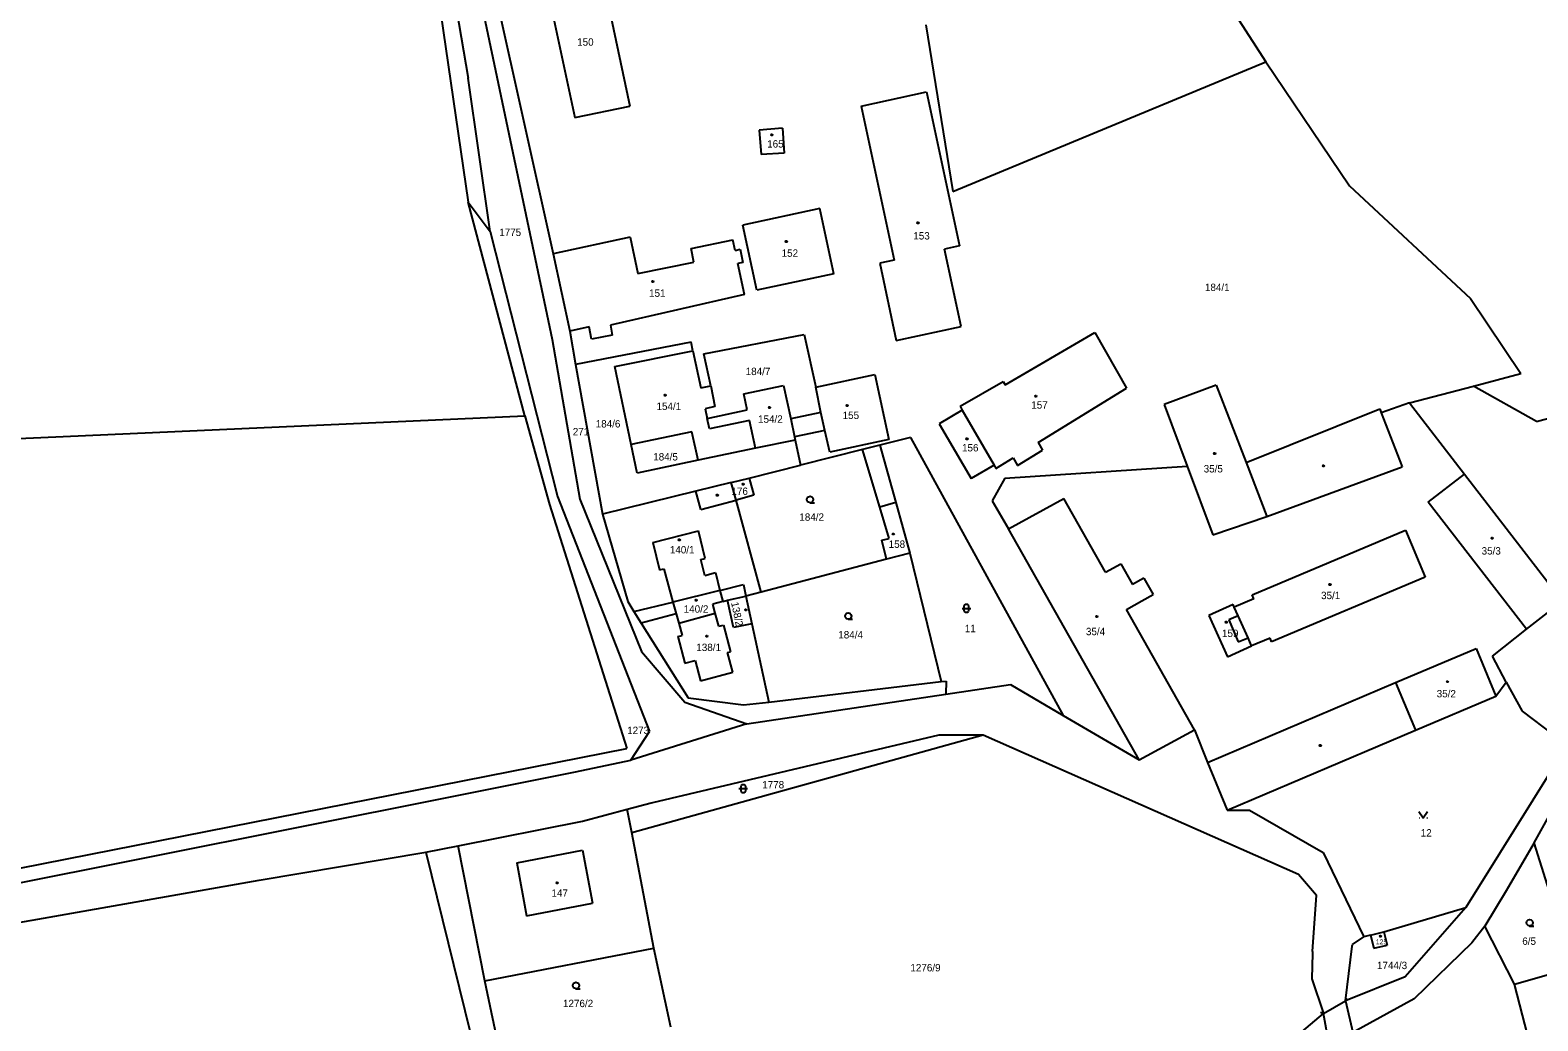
# Model space of a CAD drawing. Extents: x -799786 to -795190, y -1021716 to -1017834.
# Drawn here: x -798278.5 to -797930.9, y -1018937.1 to -1018708.6 of the extents above; entities that cross this region are included whole.
import ezdxf

# ---------------------------------------------------------------- set-up
doc = ezdxf.new("R2010")
doc.units = 0
for name, color, linetype in [('Default', 7, 'Continuous'), ('KN_HRANICE', 7, 'Continuous'), ('KN_KULTURY', 7, 'Continuous'), ('KN_PARCELY', 7, 'Continuous'), ('KN_SLUCKY', 7, 'Continuous')]:
    doc.layers.add(name, color=color, linetype=linetype)

# ---------------------------------------------------------------- blocks, each defined once
blk = doc.blocks.new('304')
at = {"layer": 'Default'}
blk.add_lwpolyline([(0, 0), (-0.38, 0.1), (-0.65, 0.37), (-0.75, 0.74), (-0.65, 1.11), (-0.38, 1.38), (-0.01, 1.48), (0.36, 1.38), (0.63, 1.11), (0.73, 0.73), (0.63, 0.35), (0.36, 0.08), (-0.02, -0.02), (0.98, -0.02)], dxfattribs=at)
blk = doc.blocks.new('314')
at = {"layer": 'Default'}
for p, q in [((-0.95, 0), (-0.85, 0)), ((0.85, 0), (0.95, 0))]:
    blk.add_line(p, q, dxfattribs=at)
blk.add_lwpolyline([(-1, 1.5), (0, 0), (1, 1.5)], dxfattribs=at)
blk = doc.blocks.new('316')
at = {"layer": 'Default'}
for points in [[(-1, 1), (0.27, 1), (1, 1)], [(-0.5, 1.5), (-0.4, 1.79), (-0.15, 1.97), (0.16, 1.97), (0.41, 1.79), (0.51, 1.5), (0.51, 0.5), (0.41, 0.21), (0.16, 0.03), (-0.15, 0.03), (-0.4, 0.21), (-0.5, 0.5), (-0.5, 1.5)]]:
    blk.add_lwpolyline(points, dxfattribs=at)
blk = doc.blocks.new('402')
at = {"layer": 'Default'}
blk.add_lwpolyline([(0.09, 0.15), (0.18, 0), (0.09, -0.15), (-0.09, -0.15), (-0.18, 0), (-0.09, 0.15), (0.09, 0.15)], dxfattribs=at)
blk = doc.blocks.new('4201')
at = {"layer": 'Default'}
blk.add_line((0, 0), (-0.5, -0.5), dxfattribs=at)

msp = doc.modelspace()

# ---------------------------------------------------------------- linework, layer by layer
at = {"layer": 'KN_HRANICE'}
for p, q in [((-798190.23, -1018645.2), (-798177.54, -1018719.73)), ((-798186.58, -1018644.89), (-798158.12, -1018780)), ((-798183.62, -1018644.7), (-798157.9, -1018760.22)), ((-798185.82, -1018691.03), (-798177.54, -1018748.29)), ((-798147.83, -1018690.52), (-798140.24, -1018726.2)), ((-798160.55, -1018693.06), (-798152.95, -1018728.8)), ((-798000.59, -1018705.06), (-797993.6, -1018715.91)), ((-798072.03, -1018707.41), (-798065.78, -1018745.87)), ((-798065.78, -1018745.87), (-797993.6, -1018715.91)), ((-797993.6, -1018715.91), (-797974.27, -1018744.5)), ((-798172.45, -1018755.08), (-798177.54, -1018719.73)), ((-798086.88, -1018726.19), (-798071.86, -1018722.86)), ((-798071.86, -1018722.86), (-798064.24, -1018758.37)), ((-798152.95, -1018728.8), (-798140.24, -1018726.2)), ((-798086.88, -1018726.19), (-798079.27, -1018761.66)), ((-798105.03, -1018731.26), (-798110.4, -1018731.68)), ((-798110.4, -1018731.68), (-798109.96, -1018737.34)), ((-798105.03, -1018731.26), (-798104.63, -1018736.97)), ((-798104.63, -1018736.97), (-798109.96, -1018737.34)), ((-797974.27, -1018744.5), (-797946.38, -1018770.53)), ((-798177.54, -1018748.29), (-798172.45, -1018755.08)), ((-798164.43, -1018797.57), (-798177.54, -1018748.29)), ((-798096.4, -1018749.79), (-798114.16, -1018753.61)), ((-798093.17, -1018764.82), (-798096.4, -1018749.79)), ((-798110.94, -1018768.57), (-798114.16, -1018753.61)), ((-798172.45, -1018755.08), (-798156.9, -1018816.15)), ((-798140.13, -1018756.39), (-798157.9, -1018760.22)), ((-798140.13, -1018756.39), (-798138.4, -1018764.79)), ((-798126.14, -1018758.95), (-798116.52, -1018756.97)), ((-798115.99, -1018759.43), (-798116.52, -1018756.97)), ((-798157.9, -1018760.22), (-798154.1, -1018778.04)), ((-798125.49, -1018762.13), (-798126.14, -1018758.95)), ((-798115.99, -1018759.43), (-798114.78, -1018759.18)), ((-798114.78, -1018759.18), (-798114.16, -1018762.18)), ((-798079.27, -1018761.66), (-798082.63, -1018762.4)), ((-798064.24, -1018758.37), (-798067.67, -1018759.12)), ((-798063.84, -1018777), (-798067.67, -1018759.12)), ((-798138.4, -1018764.79), (-798125.49, -1018762.13)), ((-798114.16, -1018762.18), (-798115.35, -1018762.42)), ((-798113.8, -1018769.59), (-798115.35, -1018762.42)), ((-798093.17, -1018764.82), (-798110.94, -1018768.57)), ((-798082.63, -1018762.4), (-798078.87, -1018780.22)), ((-798113.8, -1018769.59), (-798144.73, -1018776.67)), ((-797946.38, -1018770.53), (-797934.78, -1018787.83)), ((-798149.62, -1018777.07), (-798154.1, -1018778.04)), ((-798154.1, -1018778.04), (-798152.76, -1018785.75)), ((-798149.06, -1018779.92), (-798149.62, -1018777.07)), ((-798144.28, -1018778.95), (-798149.06, -1018779.92)), ((-798144.73, -1018776.67), (-798144.28, -1018778.95)), ((-798123.16, -1018783.29), (-798100.01, -1018778.8)), ((-798100.01, -1018778.8), (-798097.32, -1018790.95)), ((-798078.87, -1018780.22), (-798063.84, -1018777)), ((-798053.72, -1018790.43), (-798033.01, -1018778.36)), ((-798033.01, -1018778.36), (-798025.69, -1018791.2)), ((-798158.12, -1018780), (-798151.74, -1018816.81)), ((-798126.08, -1018780.59), (-798152.76, -1018785.75)), ((-798143.73, -1018786.2), (-798125.71, -1018782.56)), ((-798125.71, -1018782.56), (-798126.08, -1018780.59)), ((-798125.71, -1018782.56), (-798123.85, -1018791.14)), ((-798152.76, -1018785.75), (-798146.54, -1018820.24)), ((-798121.59, -1018790.63), (-798123.16, -1018783.29)), ((-798139.94, -1018804.21), (-798143.73, -1018786.2)), ((-798097.32, -1018790.95), (-798083.73, -1018788.02)), ((-798083.73, -1018788.02), (-798080.55, -1018803.03)), ((-797945.75, -1018790.73), (-797934.78, -1018787.83)), ((-798123.85, -1018791.14), (-798121.59, -1018790.63)), ((-798121.59, -1018790.63), (-798120.63, -1018795.46)), ((-798113.96, -1018792.51), (-798104.82, -1018790.56)), ((-798113.17, -1018796.22), (-798113.96, -1018792.51)), ((-798104.82, -1018790.56), (-798103.16, -1018798.25)), ((-798096.18, -1018796.81), (-798097.32, -1018790.95)), ((-798064.09, -1018795.36), (-798054.18, -1018789.63)), ((-798054.18, -1018789.63), (-798053.72, -1018790.43)), ((-798046.07, -1018803.73), (-798025.69, -1018791.2)), ((-798005.03, -1018790.47), (-798017.07, -1018794.94)), ((-798005.03, -1018790.47), (-797998.15, -1018808.32)), ((-797960.46, -1018794.61), (-797945.75, -1018790.73)), ((-797931.22, -1018798.88), (-797945.75, -1018790.73)), ((-797931.22, -1018798.88), (-797908.42, -1018792.81)), ((-798120.63, -1018795.46), (-798122.88, -1018795.94)), ((-798122.88, -1018795.94), (-798122.4, -1018798.19)), ((-798122.4, -1018798.19), (-798113.17, -1018796.22)), ((-798063.58, -1018796.25), (-798068.95, -1018799.39)), ((-798064.09, -1018795.36), (-798063.58, -1018796.25)), ((-798063.58, -1018796.25), (-798056.26, -1018808.98)), ((-798017.07, -1018794.94), (-798011.74, -1018809.21)), ((-797998.15, -1018808.32), (-797967.29, -1018795.96)), ((-797967.29, -1018795.96), (-797966.98, -1018796.9)), ((-797960.46, -1018794.61), (-797966.98, -1018796.9)), ((-797960.46, -1018794.61), (-797947.79, -1018811.02)), ((-798648.58, -1018819.28), (-798164.43, -1018797.57)), ((-798164.43, -1018797.57), (-798158.8, -1018818.01)), ((-798121.89, -1018800.59), (-798122.4, -1018798.19)), ((-798112.65, -1018798.62), (-798121.89, -1018800.59)), ((-798111.25, -1018805.07), (-798112.65, -1018798.62)), ((-798096.18, -1018796.81), (-798103.16, -1018798.25)), ((-798103.16, -1018798.25), (-798102.26, -1018802.39)), ((-798068.95, -1018799.39), (-798061.53, -1018812.06)), ((-798125.93, -1018801.3), (-798139.94, -1018804.21)), ((-798124.51, -1018807.83), (-798125.93, -1018801.3)), ((-798102.09, -1018803.18), (-798111.25, -1018805.07)), ((-798095.26, -1018800.95), (-798102.26, -1018802.39)), ((-798102.26, -1018802.39), (-798102.09, -1018803.18)), ((-798102.09, -1018803.18), (-798100.92, -1018808.97)), ((-798094.16, -1018805.93), (-798095.26, -1018800.95)), ((-798080.55, -1018803.03), (-798094.16, -1018805.93)), ((-798075.54, -1018802.58), (-798082.57, -1018804.35)), ((-798075.54, -1018802.58), (-798040.31, -1018866.67)), ((-798138.54, -1018810.77), (-798139.94, -1018804.21)), ((-798111.25, -1018805.07), (-798124.51, -1018807.83)), ((-798086.58, -1018805.36), (-798100.92, -1018808.97)), ((-798082.57, -1018804.35), (-798086.58, -1018805.36)), ((-798082.59, -1018818.64), (-798086.58, -1018805.36)), ((-798082.57, -1018804.35), (-798078.92, -1018817.58)), ((-798050.84, -1018809), (-798045.08, -1018805.46)), ((-798046.07, -1018803.73), (-798045.08, -1018805.46)), ((-798124.51, -1018807.83), (-798138.54, -1018810.77)), ((-798112.7, -1018811.93), (-798100.92, -1018808.97)), ((-798056.26, -1018808.98), (-798061.53, -1018812.06)), ((-798056.26, -1018808.98), (-798055.83, -1018809.73)), ((-798055.83, -1018809.73), (-798051.83, -1018807.27)), ((-798053.76, -1018811.93), (-798011.74, -1018809.21)), ((-798051.83, -1018807.27), (-798050.84, -1018809)), ((-798011.74, -1018809.21), (-798005.83, -1018825.03)), ((-797998.15, -1018808.32), (-797993.34, -1018820.8)), ((-798116.86, -1018812.97), (-798125, -1018814.96)), ((-798116.86, -1018812.97), (-798112.7, -1018811.93)), ((-798115.74, -1018817.06), (-798116.86, -1018812.97)), ((-798112.7, -1018811.93), (-798111.67, -1018815.91)), ((-798053.76, -1018811.93), (-798056.73, -1018817.15)), ((-797956.14, -1018817.47), (-797947.79, -1018811.02)), ((-797947.79, -1018811.02), (-797925.16, -1018840.33)), ((-798156.9, -1018816.15), (-798135.7, -1018870.38)), ((-798151.74, -1018816.81), (-798137.57, -1018851.92)), ((-798125, -1018814.96), (-798146.54, -1018820.24)), ((-798111.67, -1018815.91), (-798115.74, -1018817.06)), ((-798109.95, -1018838.23), (-798115.74, -1018817.06)), ((-798056.73, -1018817.15), (-798052.91, -1018823.63)), ((-798052.91, -1018823.63), (-798040.17, -1018816.67)), ((-798030.58, -1018833.65), (-798040.17, -1018816.67)), ((-798158.8, -1018818.01), (-798140.92, -1018874.27)), ((-798146.54, -1018820.24), (-798140.72, -1018840.37)), ((-798080.43, -1018825.84), (-798082.59, -1018818.64)), ((-798078.92, -1018817.58), (-798075.71, -1018829.25)), ((-798005.83, -1018825.03), (-797993.34, -1018820.8)), ((-797933.51, -1018846.78), (-797956.14, -1018817.47)), ((-798022.79, -1018876.94), (-798052.91, -1018823.63)), ((-798082.17, -1018826.29), (-798080.43, -1018825.84)), ((-798081.03, -1018830.65), (-798082.17, -1018826.29)), ((-798081.03, -1018830.65), (-798109.95, -1018838.23)), ((-798075.71, -1018829.25), (-798081.03, -1018830.65)), ((-798075.71, -1018829.25), (-798068.46, -1018858.88)), ((-798030.58, -1018833.65), (-798027.06, -1018831.73)), ((-798027.06, -1018831.73), (-798024.37, -1018836.48)), ((-798119.46, -1018837.83), (-798130.3, -1018840.54)), ((-798119.46, -1018837.83), (-798114.06, -1018836.48)), ((-798114.06, -1018836.48), (-798113.49, -1018839.16)), ((-798021.71, -1018834.99), (-798024.37, -1018836.48)), ((-798021.71, -1018834.99), (-798019.54, -1018838.82)), ((-798140.72, -1018840.37), (-798139.33, -1018842.72)), ((-798139.33, -1018842.72), (-798130.3, -1018840.54)), ((-798118.78, -1018840.42), (-798121.1, -1018841.03)), ((-798120.54, -1018843.08), (-798121.1, -1018841.03)), ((-798118.78, -1018840.42), (-798117.69, -1018840.06)), ((-798117.69, -1018840.06), (-798113.49, -1018839.16)), ((-798116.34, -1018846.42), (-798117.69, -1018840.06)), ((-798109.95, -1018838.23), (-798113.49, -1018839.16)), ((-798113.49, -1018839.16), (-798112.13, -1018845.52)), ((-798025.74, -1018842.21), (-798022.21, -1018840.28)), ((-798022.21, -1018840.28), (-798019.54, -1018838.82)), ((-798001.16, -1018841.09), (-798006.75, -1018843.6)), ((-798000.89, -1018841.68), (-798001.16, -1018841.09)), ((-797999.99, -1018843.7), (-798000.89, -1018841.68)), ((-797933.51, -1018846.78), (-797925.16, -1018840.33)), ((-798139.33, -1018842.72), (-798137.64, -1018845.36)), ((-798129.56, -1018843.25), (-798137.64, -1018845.36)), ((-798129.56, -1018843.25), (-798128.98, -1018845.39)), ((-798128.98, -1018845.39), (-798120.54, -1018843.08)), ((-798010.05, -1018869.98), (-798025.74, -1018842.21)), ((-798006.75, -1018843.6), (-798002.47, -1018853.14)), ((-797997.69, -1018848.81), (-797999.99, -1018843.7)), ((-798137.64, -1018845.36), (-798126.82, -1018862.65)), ((-798112.13, -1018845.52), (-798116.34, -1018846.42)), ((-798112.13, -1018845.52), (-798108.16, -1018863.64)), ((-797941.35, -1018853.03), (-797933.51, -1018846.78)), ((-798137.57, -1018851.92), (-798127.54, -1018863.64)), ((-798002.47, -1018853.14), (-797996.88, -1018850.63)), ((-797996.88, -1018850.63), (-797997.69, -1018848.81)), ((-797963.72, -1018859.11), (-797945.11, -1018851.21)), ((-797945.11, -1018851.21), (-797940.56, -1018862.2)), ((-797938.22, -1018858.97), (-797941.35, -1018853.03)), ((-798108.16, -1018863.64), (-798068.46, -1018858.88)), ((-798068.46, -1018858.88), (-798067.31, -1018858.75)), ((-798067.31, -1018858.75), (-798067.38, -1018861.74)), ((-797940.56, -1018862.2), (-797938.22, -1018858.97)), ((-797938.22, -1018858.97), (-797934.53, -1018865.68)), ((-798113.26, -1018868.62), (-798067.38, -1018861.74)), ((-798067.38, -1018861.74), (-798052.51, -1018859.51)), ((-798052.51, -1018859.51), (-798040.31, -1018866.67)), ((-797963.72, -1018859.11), (-797959.06, -1018870.05)), ((-797959.06, -1018870.05), (-797940.56, -1018862.2)), ((-798127.54, -1018863.64), (-798113.26, -1018868.62)), ((-798126.82, -1018862.65), (-798114.04, -1018864.2)), ((-798114.04, -1018864.2), (-798108.16, -1018863.64)), ((-797934.53, -1018865.68), (-797927.17, -1018871.24)), ((-798113.26, -1018868.62), (-798140.03, -1018876.98)), ((-798040.31, -1018866.67), (-798022.79, -1018876.94)), ((-798140.03, -1018876.98), (-798135.7, -1018870.38)), ((-798139.82, -1018893.64), (-798058.76, -1018871.15)), ((-798134.96, -1018886.72), (-798068.92, -1018871.15)), ((-798068.92, -1018871.15), (-798058.76, -1018871.15)), ((-798058.76, -1018871.15), (-797986.07, -1018903.32)), ((-798022.79, -1018876.94), (-798010.05, -1018869.98)), ((-798010.05, -1018869.98), (-798007.04, -1018877.5)), ((-798002.49, -1018888.49), (-797959.06, -1018870.05)), ((-798289.26, -1018903.57), (-798140.92, -1018874.27)), ((-797924.14, -1018873.53), (-797947.51, -1018911.01)), ((-797931.74, -1018896.06), (-797919.15, -1018873.38)), ((-798181.63, -1018885.44), (-798153.15, -1018879.76)), ((-798153.15, -1018879.76), (-798152.75, -1018879.68)), ((-798152.75, -1018879.68), (-798140.03, -1018876.98)), ((-798007.04, -1018877.5), (-798002.49, -1018888.49)), ((-798297.3, -1018908.51), (-798181.63, -1018885.44)), ((-798140.83, -1018888.32), (-798135.35, -1018886.81)), ((-798135.35, -1018886.81), (-798134.96, -1018886.72)), ((-798151.16, -1018891.06), (-798140.83, -1018888.32)), ((-798139.82, -1018893.64), (-798140.83, -1018888.32)), ((-798002.49, -1018888.49), (-797997.37, -1018888.52)), ((-797997.37, -1018888.52), (-797980.35, -1018898.3)), ((-798179.83, -1018896.78), (-798151.16, -1018891.06)), ((-798134.68, -1018920.36), (-798139.82, -1018893.64)), ((-798187.31, -1018898.18), (-798179.83, -1018896.78)), ((-798173.68, -1018927.87), (-798179.83, -1018896.78)), ((-797931.74, -1018896.06), (-797938.15, -1018907.1)), ((-797921.5, -1018928.71), (-797931.74, -1018896.06)), ((-798225.73, -1018904.69), (-798187.31, -1018898.18)), ((-798187.31, -1018898.18), (-798175.34, -1018946.72)), ((-797980.35, -1018898.3), (-797971.02, -1018917.75)), ((-797986.07, -1018903.32), (-797981.93, -1018908.1)), ((-798309.02, -1018919.33), (-798225.73, -1018904.69)), ((-797938.15, -1018907.1), (-797943.09, -1018915.31)), ((-797982.82, -1018921.11), (-797981.93, -1018908.1)), ((-797966.41, -1018916.62), (-797947.51, -1018911.01)), ((-797947.51, -1018911.01), (-797961.49, -1018926.99)), ((-797973.65, -1018919.48), (-797971.02, -1018917.75)), ((-797969.46, -1018917.34), (-797971.02, -1018917.75)), ((-797969.46, -1018917.34), (-797966.41, -1018916.62)), ((-797969.46, -1018917.34), (-797968.7, -1018920.34)), ((-797966.41, -1018916.62), (-797965.65, -1018919.63)), ((-797943.09, -1018915.31), (-797946.12, -1018919.14)), ((-797936.24, -1018928.69), (-797943.09, -1018915.31)), ((-798173.68, -1018927.87), (-798134.68, -1018920.36)), ((-798130.8, -1018938.6), (-798134.68, -1018920.36)), ((-797982.85, -1018921.51), (-797982.96, -1018927.43)), ((-797982.82, -1018921.11), (-797982.85, -1018921.51)), ((-797975.25, -1018932.49), (-797973.72, -1018919.87)), ((-797973.72, -1018919.87), (-797973.65, -1018919.48)), ((-797968.7, -1018920.34), (-797965.65, -1018919.63)), ((-797946.12, -1018919.14), (-797959.42, -1018932.05)), ((-798169.97, -1018945.48), (-798173.68, -1018927.87)), ((-797982.96, -1018927.43), (-797980.3, -1018935.41)), ((-797961.49, -1018926.99), (-797975.25, -1018932.49)), ((-797936.24, -1018928.69), (-797926.78, -1018925.98)), ((-797959.42, -1018932.05), (-797973.52, -1018939.78)), ((-797931.93, -1018945.35), (-797936.24, -1018928.69)), ((-797990.31, -1018943.91), (-797980.3, -1018935.41)), ((-797980.3, -1018935.41), (-797975.25, -1018932.49)), ((-797979.01, -1018942.65), (-797980.3, -1018935.41))]:
    msp.add_line(p, q, dxfattribs=at)
at = {"layer": 'KN_SLUCKY'}
for p, q in [((-798095.26, -1018800.95), (-798096.18, -1018796.81)), ((-797966.98, -1018796.9), (-797962.17, -1018809.38)), ((-797993.34, -1018820.8), (-797962.17, -1018809.38)), ((-798123.86, -1018819.22), (-798125, -1018814.96)), ((-798123.86, -1018819.22), (-798115.74, -1018817.06)), ((-798078.92, -1018817.58), (-798082.59, -1018818.64)), ((-798134.95, -1018826.76), (-798124.42, -1018824.13)), ((-798122.84, -1018830.46), (-798124.42, -1018824.13)), ((-797996.78, -1018838.87), (-797961.4, -1018823.98)), ((-797961.4, -1018823.98), (-797956.85, -1018834.75)), ((-798134.95, -1018826.76), (-798133.37, -1018833.09)), ((-798123.91, -1018830.73), (-798122.84, -1018830.46)), ((-798122.92, -1018834.37), (-798123.91, -1018830.73)), ((-798133.37, -1018833.09), (-798132.4, -1018832.85)), ((-798132.4, -1018832.85), (-798130.3, -1018840.54)), ((-798122.92, -1018834.37), (-798120.53, -1018833.74)), ((-798120.53, -1018833.74), (-798119.46, -1018837.83)), ((-797956.85, -1018834.75), (-797992.26, -1018849.73)), ((-798119.46, -1018837.83), (-798118.78, -1018840.42)), ((-798130.3, -1018840.54), (-798129.56, -1018843.25)), ((-797996.4, -1018839.78), (-798000.89, -1018841.68)), ((-797996.4, -1018839.78), (-797996.78, -1018838.87)), ((-798119.71, -1018846.11), (-798120.54, -1018843.08)), ((-797999.99, -1018843.7), (-798002.14, -1018844.62)), ((-798002.14, -1018844.62), (-797999.96, -1018849.72)), ((-798129.17, -1018848.47), (-798128.2, -1018848.23)), ((-798129.17, -1018848.47), (-798127.55, -1018854.6)), ((-798128.98, -1018845.39), (-798128.2, -1018848.23)), ((-798119.71, -1018846.11), (-798118.64, -1018845.84)), ((-798118.64, -1018845.84), (-798117.02, -1018851.97)), ((-798117.69, -1018852.14), (-798117.02, -1018851.97)), ((-797999.96, -1018849.72), (-797997.69, -1018848.81)), ((-797992.63, -1018848.83), (-797996.88, -1018850.63)), ((-797992.26, -1018849.73), (-797992.63, -1018848.83)), ((-798127.55, -1018854.6), (-798125.16, -1018854)), ((-798125.16, -1018854), (-798123.93, -1018858.66)), ((-798116.48, -1018856.69), (-798117.69, -1018852.14)), ((-798123.93, -1018858.66), (-798116.48, -1018856.69)), ((-798007.04, -1018877.5), (-797963.72, -1018859.11)), ((-798166.32, -1018900.65), (-798151.14, -1018897.75)), ((-798166.32, -1018900.65), (-798164.06, -1018912.9)), ((-798151.14, -1018897.75), (-798148.88, -1018910)), ((-798164.06, -1018912.9), (-798148.88, -1018910)), ((-797975.25, -1018932.49), (-797973.52, -1018939.78))]:
    msp.add_line(p, q, dxfattribs=at)

# ---------------------------------------------------------------- block references
at = {"layer": 'KN_KULTURY'}
for name, p in [('402', (-798107.48, -1018732.74)), ('402', (-798073.81, -1018753.05)), ('402', (-798104.15, -1018757.4)), ('402', (-798134.93, -1018766.62)), ('402', (-798132.08, -1018792.78)), ('402', (-798046.63, -1018793.04)), ('402', (-798108.02, -1018795.68)), ('402', (-798090.14, -1018795.19)), ('402', (-798062.49, -1018802.91)), ('402', (-798005.4, -1018806.25)), ('402', (-797980.31, -1018809.08)), ('402', (-798114.1, -1018813.31)), ('402', (-798120.08, -1018815.88)), ('304', (-798098.67, -1018817.61)), ('402', (-798128.83, -1018826.19)), ('402', (-798079.49, -1018824.83)), ('402', (-797941.43, -1018825.79)), ('402', (-797978.8, -1018836.47)), ('402', (-798124.93, -1018840.06)), ('316', (-798062.63, -1018842.99)), ('402', (-798113.52, -1018842.34)), ('304', (-798089.88, -1018844.49)), ('402', (-798032.56, -1018843.89)), ('402', (-798002.71, -1018845.2)), ('402', (-798122.51, -1018848.37)), ('402', (-797951.71, -1018858.89)), ('402', (-797981.03, -1018873.61)), ('316', (-798114.1, -1018884.56)), ('314', (-797957.3, -1018890.3)), ('402', (-798156.99, -1018905.31)), ('304', (-797932.77, -1018915.22)), ('402', (-797967.15, -1018917.59)), ('304', (-798152.65, -1018929.71))]:
    msp.add_blockref(name, p, dxfattribs=at)
at = {"layer": 'KN_SLUCKY'}
for p, rotation in [((-797975.25, -1018932.49), -171.09581500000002), ((-797980.3, -1018935.41), -64.06729900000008)]:
    msp.add_blockref('4201', p, dxfattribs=dict(at, rotation=rotation))

# ---------------------------------------------------------------- texts
at = {"layer": 'KN_PARCELY'}
for s, height, p in [('150', 1.7, (-798152.39, -1018712.22)), ('165', 1.7, (-798108.58, -1018735.71)), ('1775', 1.7, (-798170.36, -1018756.11)), ('153', 1.7, (-798074.88, -1018756.91)), ('152', 1.7, (-798105.24, -1018760.9)), ('151', 1.7, (-798135.81, -1018770.13)), ('184/1', 1.7, (-798007.64, -1018768.8)), ('184/7', 1.7, (-798113.53, -1018788.18)), ('154/1', 1.7, (-798134.09, -1018796.23)), ('157', 1.7, (-798047.68, -1018795.93)), ('184/6', 1.7, (-798148.11, -1018800.27)), ('154/2', 1.7, (-798110.68, -1018799.18)), ('155', 1.7, (-798091.18, -1018798.31)), ('271', 1.7, (-798153.4, -1018802.08)), ('184/5', 1.7, (-798134.85, -1018807.88)), ('156', 1.7, (-798063.65, -1018805.79)), ('35/5', 1.7, (-798007.93, -1018810.64)), ('176', 1.7, (-798116.81, -1018815.81)), ('184/2', 1.7, (-798101.16, -1018821.78)), ('140/1', 1.7, (-798131.02, -1018829.32)), ('158', 1.7, (-798080.56, -1018828.03)), ('35/3', 1.7, (-797943.84, -1018829.57)), ('35/1', 1.7, (-797980.86, -1018839.85)), ('140/2', 1.7, (-798127.82, -1018842.98)), ('184/4', 1.7, (-798092.18, -1018848.92)), ('11', 1.7, (-798063.02, -1018847.48)), ('35/4', 1.7, (-798035.08, -1018848.17)), ('159', 1.7, (-798003.71, -1018848.59)), ('138/1', 1.7, (-798124.91, -1018851.83)), ('35/2', 1.7, (-797954.2, -1018862.51)), ('1273', 1.7, (-798140.86, -1018870.97)), ('1778', 1.7, (-798109.72, -1018883.51)), ('12', 1.7, (-797957.88, -1018894.6)), ('147', 1.7, (-798158.31, -1018908.49)), ('6/5', 1.7, (-797934.47, -1018919.58)), ('125', 1.14, (-797968.24, -1018919.47)), ('1276/9', 1.7, (-798075.55, -1018925.71)), ('1744/3', 1.7, (-797967.97, -1018925.18)), ('1276/2', 1.7, (-798155.65, -1018933.95))]:
    msp.add_text(s, height=height, dxfattribs=at).set_placement(p)
msp.add_text('138/2', height=1.7, rotation=281.723, dxfattribs=at).set_placement((-798116.91, -1018840.67))

doc.saveas('drawing.dxf')
